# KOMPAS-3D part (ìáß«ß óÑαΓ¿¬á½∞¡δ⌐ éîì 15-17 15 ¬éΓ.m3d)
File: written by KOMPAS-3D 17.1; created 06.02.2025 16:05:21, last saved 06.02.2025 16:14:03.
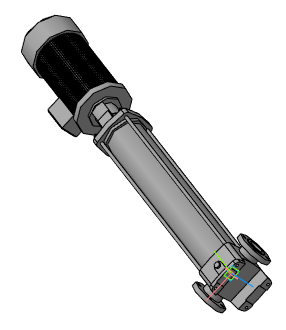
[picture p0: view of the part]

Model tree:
1. Операция без истории:1  (labels: Насос вертикальный ВМН 15-17 15 кВт)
